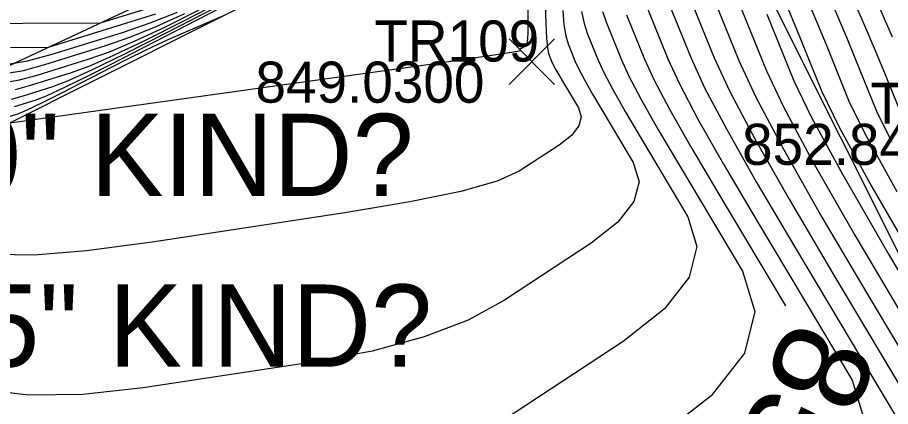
# Model space of a CAD drawing. Extents: x 1654928 to 1810050, y 486881 to 626330.
# Drawn here: x 1801402.5 to 1801428.02, y 489780.62 to 489791.98 of the extents above; entities that cross this region are included whole.
import ezdxf

# ---------------------------------------------------------------- set-up
doc = ezdxf.new("R2010")
doc.units = 0
for name, color, linetype in [('DT_X_Contour_Major', 7, 'Continuous'), ('DT_X_Contour_Minor', 7, 'Continuous'), ('RW_X_Esmt_SH', 7, 'Continuous'), ('SV_X_Random_Point', 7, 'Continuous'), ('SV_X_Text_Elevation', 7, 'Continuous'), ('SV_X_Text_Name', 7, 'Continuous'), ('SV_X_Toe_of_Slope', 7, 'Continuous'), ('SV_X_Top_of_Bank', 7, 'Continuous'), ('VG_X_Text', 7, 'Continuous')]:
    doc.layers.add(name, color=color, linetype=linetype)

msp = doc.modelspace()

# ---------------------------------------------------------------- linework, layer by layer
at = {"layer": 'DT_X_Contour_Major'}
for points in [[(1801425.574, 489795.592), (1801426.144, 489794.297), (1801426.741, 489792.938), (1801427.226, 489791.821), (1801427.599, 489790.946), (1801427.862, 489790.314), (1801428.414, 489788.95)], [(1801402.277, 489788.91), (1801412.738, 489790.368), (1801414.699, 489790.642), (1801416.098, 489790.842), (1801416.935, 489790.966), (1801417.211, 489791.015), (1801417.196, 489791.046), (1801417.196, 489791.058), (1801417.207, 489791.073), (1801417.23, 489791.091), (1801417.264, 489791.11), (1801417.37, 489791.166), (1801417.403, 489791.263), (1801417.423, 489791.511), (1801417.431, 489791.912), (1801417.426, 489792.464)], [(1801423.543, 489792.522), (1801424.39, 489790.429), (1801424.889, 489789.371), (1801425.752, 489787.769), (1801426.979, 489785.623), (1801428.57, 489782.931)], [(1801402.113, 489790.084), (1801402.554, 489790.158), (1801403.074, 489790.299), (1801404.564, 489790.762), (1801405.186, 489790.983), (1801405.935, 489791.297), (1801406.81, 489791.704), (1801407.811, 489792.205)], [(1801420.305, 489792.057), (1801420.829, 489790.762), (1801421.11, 489790.155), (1801421.56, 489789.304), (1801422.179, 489788.21), (1801422.968, 489786.872), (1801424.949, 489783.56)]]:
    msp.add_lwpolyline(points, dxfattribs=at)
at = {"layer": 'DT_X_Contour_Minor'}
for points in [[(1801402.32, 489789.602), (1801402.634, 489789.687), (1801403.534, 489789.966), (1801403.993, 489790.143), (1801404.695, 489790.461), (1801405.64, 489790.921), (1801406.827, 489791.524), (1801411.463, 489793.911)], [(1801402.437, 489789.88), (1801402.854, 489789.993), (1801404.049, 489790.364), (1801404.59, 489790.563), (1801405.315, 489790.879), (1801406.225, 489791.313), (1801407.319, 489791.865), (1801410.483, 489793.493)], [(1801422.02, 489792.9), (1801422.868, 489790.804), (1801423.323, 489789.821), (1801424.051, 489788.444), (1801425.053, 489786.673), (1801426.329, 489784.508), (1801430.096, 489778.21)], [(1801422.679, 489792.964), (1801423.585, 489790.725), (1801424.081, 489789.657), (1801424.891, 489788.134), (1801426.013, 489786.155), (1801427.449, 489783.72), (1801431.696, 489776.619)], [(1801402.212, 489791.81), (1801402.659, 489791.818), (1801404.925, 489791.825), (1801407.517, 489792.631)], [(1801421.449, 489792.619), (1801422.188, 489790.79), (1801422.585, 489789.932), (1801423.221, 489788.73), (1801424.095, 489787.185), (1801425.208, 489785.296), (1801428.496, 489779.8)], [(1801425.535, 489792.634), (1801425.859, 489791.867), (1801426.134, 489791.197), (1801426.804, 489789.541), (1801427.279, 489788.571), (1801428.202, 489786.902)], [(1801427.529, 489792.658), (1801428.071, 489791.415)], [(1801417.927, 489792.371), (1801417.942, 489791.806), (1801417.962, 489791.378), (1801417.988, 489791.087), (1801418.019, 489790.934), (1801418.111, 489790.707), (1801418.16, 489790.6), (1801418.239, 489790.451), (1801418.348, 489790.259), (1801418.486, 489790.025), (1801418.894, 489789.343), (1801418.973, 489789.083), (1801418.905, 489788.816), (1801418.69, 489788.541), (1801418.329, 489788.259), (1801417.167, 489787.495), (1801416.522, 489787.204), (1801415.457, 489786.905), (1801413.972, 489786.597), (1801412.068, 489786.28), (1801406.431, 489785.424), (1801404.512, 489785.17), (1801402.985, 489785.047), (1801401.848, 489785.058)], [(1801418.439, 489792.182), (1801418.473, 489791.768), (1801418.524, 489791.446), (1801418.591, 489791.215), (1801418.791, 489790.721), (1801418.898, 489790.489), (1801419.069, 489790.164), (1801419.306, 489789.747), (1801419.606, 489789.237), (1801420.494, 489787.752), (1801420.667, 489787.188), (1801420.519, 489786.606), (1801420.052, 489786.007), (1801419.264, 489785.392), (1801416.736, 489783.73), (1801415.675, 489783.149), (1801414.385, 489782.654), (1801412.869, 489782.243), (1801411.125, 489781.919), (1801406.171, 489781.167), (1801404.404, 489780.974), (1801402.819, 489780.959), (1801401.416, 489781.121)], [(1801402.172, 489790.611), (1801402.788, 489790.715), (1801403.514, 489790.911), (1801405.594, 489791.558), (1801406.38, 489791.823), (1801407.175, 489792.133)], [(1801402.414, 489789.38), (1801403.019, 489789.569), (1801403.349, 489789.698), (1801403.885, 489789.945), (1801404.626, 489790.309), (1801405.574, 489790.791), (1801408.375, 489792.233)], [(1801418.985, 489792.158), (1801419.06, 489791.804), (1801419.162, 489791.496), (1801419.47, 489790.734), (1801419.635, 489790.378), (1801419.9, 489789.878), (1801420.263, 489789.235), (1801420.727, 489788.449), (1801422.094, 489786.162), (1801422.361, 489785.292), (1801422.133, 489784.396), (1801421.413, 489783.474), (1801420.199, 489782.526), (1801416.305, 489779.965)], [(1801419.597, 489792.162), (1801419.734, 489791.776), (1801420.15, 489790.748), (1801420.373, 489790.266), (1801420.73, 489789.591), (1801421.221, 489788.722), (1801421.847, 489787.66), (1801423.695, 489784.572), (1801424.054, 489783.396), (1801423.747, 489782.185), (1801422.774, 489780.94), (1801421.135, 489779.66)], [(1801420.877, 489792.338), (1801421.509, 489790.776), (1801421.848, 489790.043), (1801422.39, 489789.017), (1801423.137, 489787.697), (1801424.088, 489786.084), (1801426.895, 489781.391), (1801427.442, 489779.604)], [(1801424.989, 489792.327), (1801425.271, 489791.639), (1801425.999, 489789.837), (1801426.505, 489788.8), (1801427.475, 489787.041), (1801428.911, 489784.559)], [(1801426.38, 489792.228), (1801426.729, 489791.407), (1801426.998, 489790.756), (1801427.609, 489789.246), (1801428.042, 489788.361)], [(1801402.142, 489790.347), (1801402.671, 489790.436), (1801403.294, 489790.605), (1801405.079, 489791.16), (1801405.783, 489791.403), (1801406.555, 489791.715), (1801407.394, 489792.096)], [(1801402.194, 489789.074), (1801402.504, 489789.171), (1801402.673, 489789.237), (1801402.947, 489789.363), (1801403.327, 489789.55), (1801403.812, 489789.797), (1801405.247, 489790.535), (1801405.76, 489790.796), (1801406.221, 489791.023), (1801406.631, 489791.217), (1801406.99, 489791.378), (1801408.546, 489792.054)], [(1801402.297, 489791.11), (1801403.401, 489791.114), (1801406.544, 489792.091)], [(1801424.407, 489792.081), (1801425.194, 489790.133), (1801425.697, 489789.086), (1801426.614, 489787.405), (1801427.945, 489785.091), (1801429.69, 489782.143)]]:
    msp.add_lwpolyline(points, dxfattribs=at)
at = {"layer": 'RW_X_Esmt_SH'}
msp.add_line((1801533.563, 489574.54), (1801308.538, 490024.454), dxfattribs=at)
at = {"layer": 'SV_X_Random_Point'}
for p, q in [((1801416.867, 489790.027), (1801418.2, 489791.362)), ((1801416.867, 489791.362), (1801418.2, 489790.027))]:
    msp.add_line(p, q, dxfattribs=at)
at = {"layer": 'SV_X_Toe_of_Slope'}
msp.add_lwpolyline([(1801417.791, 489799.995), (1801412.832, 489796.754), (1801412.089, 489795.17), (1801401.953, 489790.438), (1801397.863, 489793.263), (1801395.881, 489794.687), (1801394.491, 489796.208), (1801381.141, 489790.72), (1801379.18, 489788.057), (1801375.237, 489785.681), (1801360.556, 489782.746), (1801350.439, 489783.352), (1801348.143, 489785.528), (1801335.479, 489785.306), (1801328.907, 489786.007), (1801321.924, 489784.909)], dxfattribs=at)
at = {"layer": 'SV_X_Top_of_Bank'}
msp.add_lwpolyline([(1801414.708, 489795.331), (1801414.041, 489794.432), (1801412.967, 489794.649), (1801413.875, 489794.726), (1801401.963, 489788.753), (1801387.705, 489783.674), (1801376.875, 489783.007), (1801368.983, 489780.458), (1801361.095, 489781.125), (1801348.111, 489781.288), (1801336.05, 489778.687), (1801318.855, 489781.567)], dxfattribs=at)

# ---------------------------------------------------------------- texts
at = {"layer": 'DT_X_Contour_Major'}
msp.add_text('850', height=2.8, rotation=246.987, dxfattribs=at).set_placement((1801425.117, 489783.248))
at = {"layer": 'SV_X_Text_Elevation'}
for s, p in [('849.0300', (1801409.455, 489789.495)), ('852.8400', (1801423.679, 489787.679))]:
    msp.add_text(s, height=1.2, dxfattribs=at).set_placement(p)
at = {"layer": 'SV_X_Text_Name'}
for s, p in [('TR109', (1801412.933, 489790.695)), ('TR101', (1801427.43, 489788.879))]:
    msp.add_text(s, height=1.2, dxfattribs=at).set_placement(p)
at = {"layer": 'VG_X_Text'}
for s, p in [('SIZE? 10" KIND?', (1801389.219, 489786.77)), ('SIZE? 15" KIND?', (1801389.758, 489781.786))]:
    msp.add_text(s, height=2.4, dxfattribs=at).set_placement(p)

doc.saveas('drawing.dxf')
